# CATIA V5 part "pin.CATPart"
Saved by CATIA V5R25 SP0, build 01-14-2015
Part number: pin
Bounding box of the stored display mesh (mm): x -16 to 16, y -5 to 5, z -5 to 5
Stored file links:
  C:\Users\feridun\Desktop\krank biyel\pin.CATPart
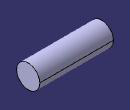
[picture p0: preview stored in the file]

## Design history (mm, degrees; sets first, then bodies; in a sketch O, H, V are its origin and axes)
Body1 (main body)
  Sketch1 on yz-plane, origin (0, 0, 0), H (0, 1, 0), V (0, 0, 1)
    circle A1 centre (0, 0) radius 5
    point P1 (5, 0)
    radius A1 = 5
    coincidence: A1 P1, P1 H
  Pad1: profile Sketch1, direction (1, 0, 0), length 16, mirrored extent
